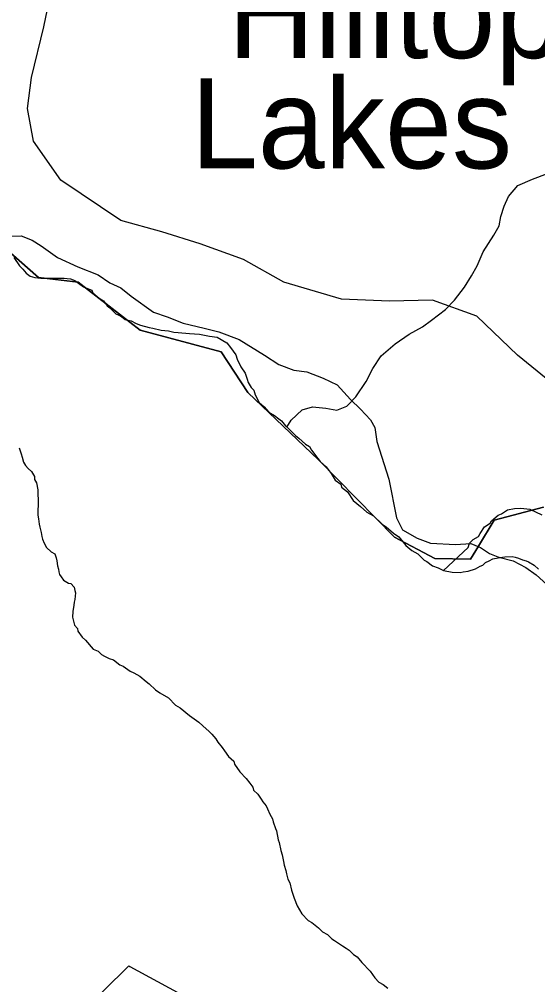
# Model space of a CAD drawing. Extents: x 0 to 34, y 0 to 22.
# Drawn here: x 4.944 to 5.489, y 18.554 to 19.569 of the extents above; entities that cross this region are included whole.
import ezdxf

# ---------------------------------------------------------------- set-up
doc = ezdxf.new("R2010")
doc.units = 0
for name, color, linetype in [('GM_X_Corporation', 7, 'Continuous'), ('GM_X_Minor_Lake_Text', 7, 'Continuous'), ('GM_X_Minor_River', 7, 'Continuous'), ('GM_X_Rail_Line', 7, 'Continuous'), ('GM_X_Township_Road', 7, 'Continuous')]:
    doc.layers.add(name, color=color, linetype=linetype)

msp = doc.modelspace()

# ---------------------------------------------------------------- linework, layer by layer
at = {"layer": 'GM_X_Corporation'}
for points in [[(5.4955, 19.0564), (5.4436, 19.0427), (5.4269, 19.0153), (5.4187, 19.0017), (5.3811, 19.0023), (5.3385, 19.0249), (5.2587, 19.1062), (5.1844, 19.1771), (5.1565, 19.2197), (5.0713, 19.2426), (5.0059, 19.2929), (4.9642, 19.2981), (4.9352, 19.3234)], [(4.9352, 19.3234), (4.9642, 19.2981), (5.0059, 19.2929), (5.0713, 19.2426), (5.1565, 19.2197), (5.1844, 19.1771), (5.2587, 19.1062), (5.3385, 19.0249), (5.3811, 19.0023), (5.4187, 19.0017), (5.4269, 19.0153), (5.4436, 19.0427), (5.4955, 19.0564)], [(4.9788, 18.495), (5.0593, 18.574), (5.0604, 18.5734), (5.1805, 18.5081)]]:
    msp.add_lwpolyline(points, dxfattribs=at)
at = {"layer": 'GM_X_Minor_River'}
for points in [[(5.2255, 19.1404), (5.2301, 19.1479), (5.2414, 19.1587), (5.2525, 19.1619), (5.2665, 19.1605), (5.2779, 19.1584), (5.2886, 19.1628), (5.2979, 19.1725), (5.3088, 19.1887), (5.3159, 19.2022), (5.3245, 19.2154), (5.3392, 19.2281), (5.3542, 19.2384), (5.3681, 19.2462), (5.3777, 19.2532), (5.3923, 19.2644), (5.4016, 19.2741), (5.4122, 19.2876), (5.4196, 19.2996), (5.4255, 19.3102), (5.4318, 19.3249), (5.4432, 19.3426), (5.4487, 19.3524), (5.4504, 19.3622), (5.454, 19.3728), (5.4587, 19.383), (5.4684, 19.3946), (5.4838, 19.4015), (5.4995, 19.4073)], [(4.9384, 19.3191), (4.9443, 19.3103), (4.9477, 19.3068), (4.9511, 19.3025), (4.9556, 19.2994), (4.9605, 19.2978), (4.9666, 19.2973), (4.9783, 19.2971), (4.9833, 19.2974), (4.9863, 19.2974), (4.9913, 19.2973), (4.9943, 19.2968), (4.9977, 19.2964), (5.0026, 19.2948), (5.0116, 19.2882), (5.0203, 19.2846), (5.0214, 19.2819), (5.0282, 19.2761), (5.0327, 19.2733), (5.0364, 19.2683), (5.0394, 19.266), (5.0454, 19.2598), (5.048, 19.2586), (5.0518, 19.2567), (5.0555, 19.2539), (5.0616, 19.2523), (5.0669, 19.2495), (5.0714, 19.2479), (5.0805, 19.2455), (5.0843, 19.2447), (5.0934, 19.2426), (5.101, 19.2417), (5.1066, 19.2405), (5.1112, 19.24), (5.123, 19.239), (5.1336, 19.2385), (5.1442, 19.2364), (5.1522, 19.2351), (5.1623, 19.2292), (5.1661, 19.2242), (5.1716, 19.2165), (5.1731, 19.2119), (5.1771, 19.2039), (5.1816, 19.1973), (5.1837, 19.1912), (5.1848, 19.1874), (5.1878, 19.1824), (5.1908, 19.1793), (5.1922, 19.1747), (5.1963, 19.1666), (5.2015, 19.162), (5.2063, 19.1562), (5.2124, 19.1527), (5.2169, 19.1492), (5.2199, 19.1472), (5.224, 19.1418), (5.227, 19.1391), (5.2344, 19.1317), (5.2382, 19.129), (5.2449, 19.1228), (5.2491, 19.1204), (5.2513, 19.1162), (5.258, 19.1077), (5.2606, 19.1043), (5.2666, 19.0988), (5.2722, 19.0919), (5.2762, 19.085), (5.2822, 19.0807), (5.283, 19.0776), (5.2893, 19.0726), (5.2953, 19.0633), (5.3028, 19.0571), (5.3095, 19.0513), (5.3167, 19.0474), (5.3256, 19.0385), (5.3298, 19.0357), (5.3376, 19.0291), (5.3433, 19.0252), (5.3477, 19.0198), (5.3507, 19.0163), (5.3567, 19.0109), (5.3631, 19.0074), (5.3699, 19.0008), (5.3725, 18.9992), (5.3785, 18.9949), (5.3845, 18.9925), (5.3902, 18.9898), (5.3993, 18.9881), (5.4077, 18.9879), (5.4107, 18.9883), (5.416, 18.9893), (5.4237, 18.9915), (5.4287, 18.9944), (5.4317, 18.9955), (5.4344, 18.9981), (5.4383, 19), (5.4421, 19.0022)], [(4.9438, 19.119), (4.9459, 19.1125), (4.947, 19.109), (4.9485, 19.1037), (4.9507, 19.1002), (4.9533, 19.0971), (4.957, 19.094), (4.96, 19.0886), (4.9599, 19.0856), (4.9622, 19.0821), (4.9636, 19.0745), (4.9635, 19.0703), (4.9638, 19.0638), (4.9635, 19.0479), (4.9642, 19.0441), (4.9649, 19.0387), (4.9656, 19.0353), (4.967, 19.0299), (4.9677, 19.0257), (4.9684, 19.0227), (4.9702, 19.0185), (4.9728, 19.0142), (4.9777, 19.0096), (4.9814, 19.0072), (4.9829, 19.003), (4.9836, 19), (4.9843, 18.9946), (4.9853, 18.9912), (4.9857, 18.9885), (4.9864, 18.9858), (4.9879, 18.9832), (4.9905, 18.9797), (4.9957, 18.9766), (4.9984, 18.9761), (5.0017, 18.9723), (5.0024, 18.9688), (5.0032, 18.9662), (5.0023, 18.9593), (5.0019, 18.9567), (5.0014, 18.9533), (5.0002, 18.9468), (5.0001, 18.9407), (5.0008, 18.9381), (5.0022, 18.9323), (5.0052, 18.9288), (5.0055, 18.9262), (5.01, 18.9196), (5.0137, 18.9165), (5.0216, 18.9073), (5.0268, 18.9049), (5.0306, 18.9014), (5.0336, 18.8998), (5.0385, 18.8974), (5.043, 18.8958), (5.0498, 18.8908), (5.0532, 18.8892), (5.0607, 18.8841), (5.0645, 18.8822), (5.0709, 18.8786), (5.0776, 18.8732), (5.0806, 18.8708), (5.0874, 18.8643), (5.0919, 18.8611), (5.1009, 18.856), (5.1084, 18.8483), (5.1133, 18.8455), (5.123, 18.8374), (5.1328, 18.8304), (5.1369, 18.8265), (5.1437, 18.8207), (5.1466, 18.8176), (5.1507, 18.8129), (5.153, 18.8095)], [(5.3902, 18.9898), (5.4161, 19.014), (5.4177, 19.0186), (5.4215, 19.0223), (5.4269, 19.0256), (5.4289, 19.0287), (5.4332, 19.0358), (5.4393, 19.0395), (5.4405, 19.0421), (5.4478, 19.0481), (5.4513, 19.0496), (5.4574, 19.0536), (5.4647, 19.055), (5.4715, 19.0553), (5.481, 19.0544), (5.4935, 19.0484)], [(5.4421, 19.0022), (5.4478, 19.0032), (5.4547, 19.0042), (5.4623, 19.0045), (5.4657, 19.004), (5.4691, 19.0028), (5.4733, 19.0012), (5.4771, 19), (5.4797, 18.9989), (5.4857, 18.9953), (5.4902, 18.9911)], [(5.153, 18.8095), (5.1574, 18.8037), (5.1597, 18.8002), (5.1641, 18.7941), (5.1697, 18.7894), (5.1704, 18.7863), (5.176, 18.7783), (5.1827, 18.7713), (5.1865, 18.7663), (5.1898, 18.762), (5.1905, 18.759), (5.195, 18.7547), (5.1983, 18.7493), (5.2002, 18.7466), (5.2035, 18.7424), (5.205, 18.7393), (5.2076, 18.7336), (5.2105, 18.7286), (5.2112, 18.7255), (5.2134, 18.7187), (5.2145, 18.716), (5.2162, 18.7068), (5.2173, 18.7037), (5.2191, 18.6953), (5.2205, 18.6908), (5.2219, 18.6839), (5.2226, 18.6801), (5.2244, 18.6743), (5.2251, 18.6709), (5.2266, 18.6652), (5.2284, 18.6613), (5.2302, 18.6537), (5.2331, 18.6453), (5.2364, 18.6372), (5.2412, 18.6288), (5.2479, 18.6218), (5.2517, 18.6198), (5.2588, 18.614), (5.2629, 18.6098), (5.2682, 18.607), (5.2727, 18.6027), (5.2757, 18.6008), (5.2809, 18.5973), (5.2839, 18.5953), (5.2877, 18.5926), (5.2911, 18.5906), (5.2956, 18.586), (5.2993, 18.5836), (5.3042, 18.5778), (5.3131, 18.5686), (5.3154, 18.5651), (5.318, 18.5616), (5.3221, 18.557), (5.3266, 18.5546), (5.3315, 18.5507)]]:
    msp.add_lwpolyline(points, dxfattribs=at)
at = {"layer": 'GM_X_Rail_Line'}
msp.add_lwpolyline([(5.498, 19.1918), (5.4679, 19.2162), (5.4252, 19.2573), (5.3786, 19.274), (5.3333, 19.273), (5.283, 19.2751), (5.2223, 19.2931), (5.1798, 19.3167), (5.1342, 19.3333), (5.0938, 19.3458), (5.0507, 19.3577), (4.9877, 19.4002), (4.9588, 19.4412), (4.9525, 19.4758), (4.9569, 19.5081), (4.9699, 19.5616), (4.9877, 19.6476)], dxfattribs=at)
at = {"layer": 'GM_X_Township_Road'}
for points in [[(4.9346, 19.3415), (4.9461, 19.3418), (4.9576, 19.3373), (4.9671, 19.3311), (4.9842, 19.3188), (5.0055, 19.3091), (5.0271, 19.3009), (5.0393, 19.2922), (5.0508, 19.2869), (5.0616, 19.2784), (5.085, 19.2615), (5.0997, 19.2565), (5.1165, 19.25), (5.1386, 19.2447), (5.1539, 19.2408), (5.1751, 19.2328), (5.202, 19.2163), (5.217, 19.2066), (5.2329, 19.2004), (5.2464, 19.1986), (5.2635, 19.1922), (5.2783, 19.1851), (5.2922, 19.1697), (5.3029, 19.1594), (5.3135, 19.1483), (5.3179, 19.1403), (5.32, 19.1255), (5.3326, 19.0859), (5.3409, 19.0452), (5.347, 19.0325), (5.3624, 19.024), (5.3765, 19.0186), (5.4027, 19.0171), (5.4189, 19.0181), (5.4272, 19.0147), (5.4291, 19.014), (5.4386, 19.0078), (5.4473, 19.0042)], [(5.4473, 19.0042), (5.4483, 19.0038), (5.4633, 18.9999), (5.4766, 18.9931), (5.4878, 18.9854), (5.499, 18.9752), (5.5165, 18.9597), (5.5296, 18.9482), (5.5332, 18.94), (5.5367, 18.933), (5.5396, 18.9278), (5.5466, 18.9205), (5.5589, 18.913), (5.5708, 18.9076), (5.5788, 18.8996)]]:
    msp.add_lwpolyline(points, dxfattribs=at)

# ---------------------------------------------------------------- texts
at = {"layer": 'GM_X_Minor_Lake_Text'}
for s, p in [('Hilltop', (5.1633, 19.5287)), ('Lakes', (5.1245, 19.4127))]:
    msp.add_text(s, height=0.09469, rotation=359.9965, dxfattribs=at).set_placement(p)

doc.saveas('drawing.dxf')
